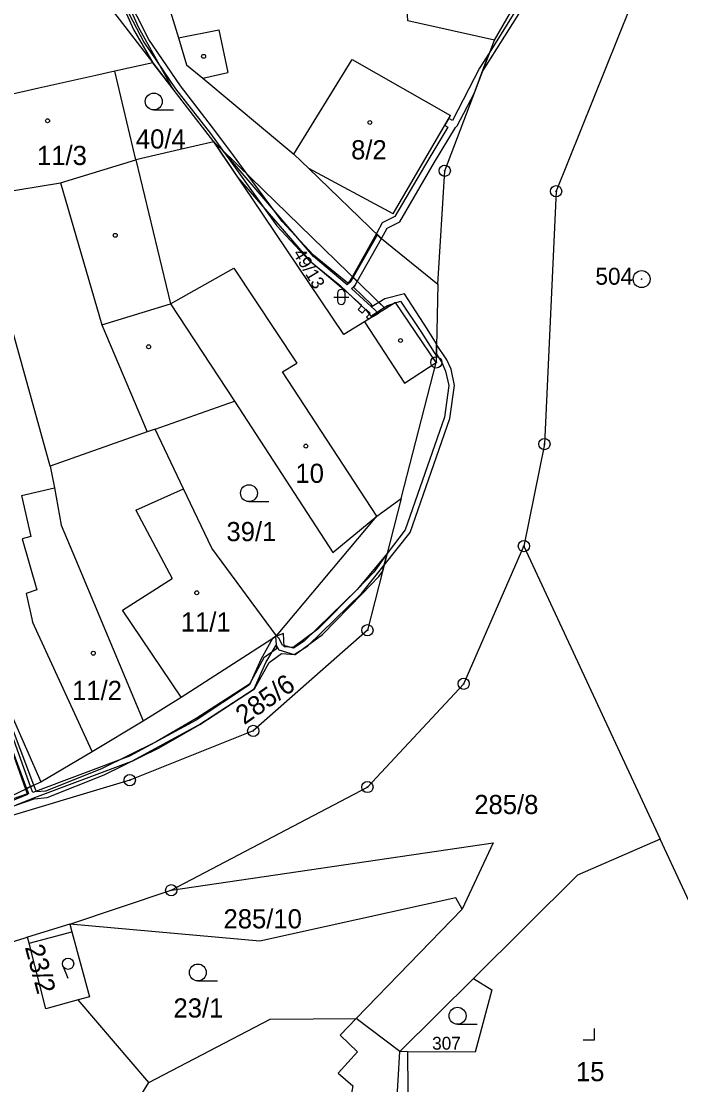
# Model space of a CAD drawing. Extents: x -779723 to -777378, y -1011169 to -1009297.
# Drawn here: x -779071.4 to -779012.9, y -1010301.7 to -1010207.4 of the extents above; entities that cross this region are included whole.
import ezdxf

# ---------------------------------------------------------------- set-up
doc = ezdxf.new("R2010")
doc.units = 0
for name, color, linetype in [('Hranice parcel', 7, 'Continuous'), ('Parcelní čísla', 7, 'Continuous'), ('Vnitřní kresba', 7, 'Continuous'), ('Věcná břemena k části', 7, 'Continuous'), ('Značky bodu BP', 7, 'Continuous'), ('Značky budov', 7, 'Continuous'), ('Značky kultur', 7, 'Continuous')]:
    doc.layers.add(name, color=color, linetype=linetype)

msp = doc.modelspace()

# ---------------------------------------------------------------- linework, layer by layer
at = {"layer": 'Hranice parcel'}
for p, q in [((-779029.4, -1010209.06), (-779023.53, -1010198.94)), ((-779059.7, -1010211.07), (-779063.08, -1010211.82)), ((-779054.29, -1010218.08), (-779059.7, -1010211.07)), ((-779061.2, -1010219.69), (-779063.08, -1010211.82)), ((-779039.06, -1010232.9), (-779054.29, -1010218.08)), ((-779034.42, -1010230.71), (-779034.55, -1010237.65)), ((-779068.8, -1010246.85), (-779072.13, -1010234.9)), ((-779037.66, -1010249.73), (-779034.55, -1010237.65)), ((-779059.5, -1010243.56), (-779052.46, -1010241.08)), ((-779039.84, -1010251.3), (-779037.66, -1010249.73)), ((-779048.74, -1010261.92), (-779039.84, -1010251.3)), ((-779026.78, -1010253.95), (-779014.69, -1010279.95)), ((-779065.1, -1010272.18), (-779060.55, -1010269.44)), ((-779069.64, -1010274.85), (-779065.1, -1010272.18)), ((-779073.55, -1010276.72), (-779069.64, -1010274.85)), ((-779009.89, -1010290.29), (-779014.69, -1010279.95)), ((-779067.08, -1010287.5), (-779058.07, -1010284.48)), ((-779041.67, -1010295.86), (-779032.26, -1010286.16)), ((-779067.08, -1010287.5), (-779070.83, -1010288.65)), ((-779037.78, -1010298.79), (-779031.26, -1010292.31)), ((-779060.06, -1010301.54), (-779066.34, -1010294.21)), ((-779037.78, -1010298.79), (-779041.67, -1010295.86)), ((-779038.46, -1010309.75), (-779037.78, -1010298.79)), ((-779037.1, -1010298.8), (-779037.78, -1010298.79))]:
    msp.add_line(p, q, dxfattribs=at)
for points in [[(-778951.52, -1010304.9), (-778950.58, -1010287.37), (-778950.58, -1010286.9), (-778950.34, -1010251.89), (-778953.35, -1010232.46), (-778955.45, -1010215), (-778962.68, -1010202.09), (-778972.6, -1010193.75), (-778987.54, -1010189.4), (-778999.84, -1010191.68), (-779009.45, -1010195.21), (-779017.34, -1010206.13), (-779023.92, -1010222.47), (-779024.96, -1010244.9), (-779026.78, -1010253.95)], [(-779029.4, -1010209.06), (-779037.09, -1010207.36), (-779037.33, -1010202.84), (-779037.65, -1010196.93), (-779037.72, -1010195.64)], [(-779067.78, -1010200.61), (-779062.19, -1010207.85), (-779059.7, -1010211.07)], [(-779058.6, -1010204.99), (-779057.43, -1010208.85), (-779056.71, -1010211.24), (-779055.26, -1010212.45), (-779047.2, -1010219.18), (-779045.87, -1010220.45), (-779039.55, -1010226.53), (-779034.42, -1010230.71)], [(-779034.42, -1010230.71), (-779033.8, -1010220.65), (-779029.4, -1010209.06)], [(-779063.08, -1010211.82), (-779064.77, -1010212.2), (-779069.82, -1010213.33), (-779076.2, -1010214.76)], [(-779054.29, -1010218.08), (-779057.29, -1010218.78), (-779061.2, -1010219.69)], [(-779039.06, -1010232.9), (-779040.92, -1010234.04), (-779042.77, -1010235.17), (-779050.87, -1010223.15), (-779054.29, -1010218.08)], [(-779061.2, -1010219.69), (-779058.14, -1010232.46), (-779052.46, -1010241.08)], [(-779034.55, -1010237.65), (-779038.16, -1010232.35), (-779039.06, -1010232.9)], [(-779052.46, -1010241.08), (-779043.73, -1010254.53), (-779039.84, -1010251.3)], [(-779059.5, -1010243.56), (-779060.22, -1010243.82), (-779068.8, -1010246.85)], [(-779048.74, -1010261.92), (-779054.48, -1010254.13), (-779056.98, -1010248.86), (-779059.5, -1010243.56)], [(-779068.8, -1010246.85), (-779068.44, -1010248.79), (-779067.83, -1010252.08), (-779066.56, -1010255.1), (-779060.55, -1010269.44)], [(-779037.66, -1010249.73), (-779040.66, -1010261.41), (-779050.79, -1010270.34), (-779061.75, -1010274.71), (-779086.5, -1010282.14)], [(-779076.54, -1010251.4), (-779075.23, -1010259.6), (-779074.39, -1010263.13), (-779072.64, -1010267.9), (-779072.39, -1010268.55), (-779072.2, -1010269.07), (-779069.64, -1010274.85)], [(-779058.07, -1010284.48), (-779040.66, -1010275.32), (-779032.12, -1010266.16), (-779026.78, -1010253.95)], [(-779060.55, -1010269.44), (-779057.2, -1010267.35), (-779048.74, -1010261.92)], [(-779014.69, -1010279.95), (-779022.02, -1010283.13), (-779031.26, -1010292.31)], [(-779058.07, -1010284.48), (-779029.51, -1010280.26), (-779032.26, -1010286.16)], [(-779032.26, -1010286.16), (-779032.82, -1010285.16), (-779050.21, -1010289), (-779067.08, -1010287.5)], [(-779067.08, -1010287.5), (-779066.89, -1010288.17), (-779065.31, -1010293.92), (-779066.34, -1010294.21)], [(-779070.83, -1010288.65), (-779071.05, -1010288.72), (-779076.63, -1010290.43), (-779079.33, -1010290.64), (-779090.04, -1010291.48)], [(-779066.34, -1010294.21), (-779069.19, -1010295.01), (-779070.69, -1010289.16), (-779070.83, -1010288.65)], [(-779037.1, -1010298.8), (-779036.94, -1010319.12), (-779030.77, -1010318.99), (-779025.76, -1010314.84), (-779021.61, -1010311.89), (-779003.74, -1010303.52), (-779004.9, -1010301.02), (-779009.89, -1010290.29)], [(-779031.26, -1010292.31), (-779029.63, -1010293.31), (-779031.09, -1010298.84), (-779037.1, -1010298.8)], [(-779041.67, -1010295.86), (-779043.09, -1010297.32), (-779041.55, -1010298.82), (-779043.27, -1010300.7), (-779041.95, -1010301.84), (-779043.36, -1010309.37), (-779048.83, -1010303.23), (-779063.1, -1010315.51), (-779057.77, -1010321.93), (-779062.91, -1010326.41), (-779058.85, -1010331.38)], [(-779060.06, -1010301.54), (-779049.3, -1010295.9), (-779041.67, -1010295.86)], [(-779095.54, -1010337.04), (-779070.4, -1010318.23), (-779060.06, -1010301.54)]]:
    msp.add_lwpolyline(points, dxfattribs=at)
at = {"layer": 'Vnitřní kresba'}
for p, q in [((-779057.43, -1010208.85), (-779053.86, -1010208.15)), ((-779053.86, -1010208.15), (-779053.04, -1010211.92)), ((-779047.2, -1010219.18), (-779042.03, -1010210.78)), ((-779042.03, -1010210.78), (-779033.28, -1010215.75)), ((-779055.26, -1010212.45), (-779053.04, -1010211.92)), ((-779038.39, -1010224.47), (-779033.28, -1010215.75)), ((-779067.91, -1010221.73), (-779061.2, -1010219.69)), ((-779038.39, -1010224.47), (-779045.87, -1010220.45)), ((-779074.94, -1010222.88), (-779067.91, -1010221.73)), ((-779067.91, -1010221.73), (-779064.23, -1010234.32)), ((-779058.14, -1010232.46), (-779052.52, -1010229.28)), ((-779052.52, -1010229.28), (-779046.93, -1010237.71)), ((-779064.23, -1010234.32), (-779058.14, -1010232.46)), ((-779064.23, -1010234.32), (-779060.22, -1010243.82)), ((-779040.92, -1010234.04), (-779037.38, -1010239.5)), ((-779037.38, -1010239.5), (-779034.55, -1010237.65)), ((-779048.2, -1010238.48), (-779046.93, -1010237.71)), ((-779039.84, -1010251.3), (-779048.2, -1010238.48)), ((-779071.35, -1010249.46), (-779068.44, -1010248.79)), ((-779061.2, -1010250.75), (-779056.98, -1010248.86)), ((-779061.2, -1010250.75), (-779057.98, -1010256.83)), ((-779062.39, -1010259.63), (-779057.98, -1010256.83)), ((-779057.2, -1010267.35), (-779062.39, -1010259.63)), ((-779065.1, -1010272.18), (-779070.38, -1010260.68)), ((-779070.69, -1010289.16), (-779066.89, -1010288.17))]:
    msp.add_line(p, q, dxfattribs=at)
msp.add_lwpolyline([(-779071.35, -1010249.46), (-779070.54, -1010253.09), (-779071.3, -1010253.31), (-779070, -1010257.83), (-779070.95, -1010258.14), (-779070.38, -1010260.68)], dxfattribs=at)
at = {"layer": 'Věcná břemena k části'}
for points in [[(-779030.46, -1010211.85), (-779022.51, -1010199.29), (-779020.23, -1010195.48), (-779019.73, -1010194.2), (-779020.75, -1010195.48), (-779022.93, -1010199.03), (-779029.85, -1010210.23)], [(-779057.92, -1010213.38), (-779060.97, -1010207.9), (-779063.22, -1010202.83), (-779063.98, -1010199.42), (-779064.47, -1010199.57), (-779063.7, -1010202.99), (-779061.41, -1010208.12), (-779059.7, -1010211.07)], [(-779051.34, -1010220.95), (-779052.56, -1010219.3), (-779054.19, -1010217.07), (-779057.26, -1010213.11), (-779060.05, -1010209.02), (-779063.16, -1010202.87), (-779063.71, -1010199.33), (-779064.28, -1010199.51), (-779063.74, -1010203.05), (-779060.51, -1010209.23), (-779057.68, -1010213.39), (-779054.6, -1010217.35), (-779053.53, -1010218.82)], [(-779039.41, -1010226.65), (-779038.9, -1010225.74), (-779037.8, -1010225.17), (-779034.7, -1010219.9), (-779032.85, -1010216.81), (-779032.7, -1010216.68), (-779031.2, -1010213.79), (-779029.85, -1010210.23), (-779030.71, -1010211.56), (-779033.12, -1010216.19), (-779033.44, -1010216.02), (-779033.8, -1010216.63), (-779033.53, -1010216.77), (-779035.22, -1010219.6), (-779038.22, -1010224.71), (-779039.34, -1010225.28), (-779039.87, -1010226.22)], [(-779040.11, -1010233.54), (-779039.68, -1010233.28), (-779040.65, -1010232.41), (-779042.08, -1010231.1), (-779041.79, -1010230.85), (-779041.56, -1010230.47), (-779041.94, -1010230.1), (-779042.19, -1010230.53), (-779042.46, -1010230.77), (-779045.46, -1010228.27), (-779053.53, -1010218.82), (-779054.29, -1010218.08), (-779052.18, -1010221.21), (-779045.81, -1010228.62), (-779042.6, -1010231.29), (-779041.17, -1010232.6), (-779041.49, -1010232.95), (-779041.13, -1010233.29), (-779040.8, -1010232.94), (-779040.43, -1010233.28), (-779040.73, -1010233.63), (-779040.53, -1010233.8)], [(-779039.17, -1010232.79), (-779039.64, -1010232.33), (-779040.23, -1010232.69), (-779040.29, -1010232.51), (-779041.91, -1010230.98), (-779041.73, -1010230.78), (-779041.56, -1010230.47), (-779042, -1010230.04), (-779042.21, -1010230.42), (-779042.4, -1010230.62), (-779045.45, -1010228.13), (-779048.24, -1010225.15), (-779051.34, -1010220.95), (-779053.53, -1010218.82), (-779052.96, -1010219.6), (-779048.7, -1010225.55), (-779045.87, -1010228.57), (-779043.09, -1010230.83), (-779040.77, -1010233.03), (-779040.36, -1010233.54)], [(-779039.41, -1010226.65), (-779039.55, -1010226.53), (-779039.87, -1010226.22), (-779042, -1010230.04), (-779041.56, -1010230.47)], [(-779039.41, -1010226.65), (-779039.55, -1010226.53), (-779039.78, -1010226.3), (-779041.94, -1010230.1), (-779041.56, -1010230.47)], [(-779034.54, -1010237.09), (-779034.52, -1010235.99), (-779035.35, -1010234.67), (-779037.38, -1010231.56), (-779039.12, -1010232.01), (-779039.64, -1010232.33), (-779039.17, -1010232.79), (-779038.88, -1010232.61), (-779037.73, -1010232.21), (-779035.85, -1010234.99)], [(-779032.93, -1010239.69), (-779033.24, -1010238.26), (-779033.62, -1010237.42), (-779034.52, -1010236.06), (-779034.54, -1010236.93), (-779034.05, -1010237.66), (-779033.72, -1010238.42), (-779033.43, -1010239.71), (-779033.82, -1010242.51), (-779037.32, -1010252.51), (-779038.91, -1010254.59), (-779039.17, -1010255.63), (-779036.88, -1010252.75), (-779033.34, -1010242.63)], [(-779086.16, -1010255.06), (-779081.79, -1010253.63), (-779080.27, -1010253.17), (-779077.7, -1010252.31), (-779075.82, -1010261.01), (-779073.45, -1010268.66), (-779071, -1010275.5), (-779070.55, -1010275.28), (-779072.9, -1010268.73), (-779072.39, -1010268.55), (-779072.58, -1010268.05), (-779073.06, -1010268.25), (-779075.34, -1010260.89), (-779077.32, -1010251.65), (-779080.43, -1010252.7), (-779081.71, -1010253.08), (-779082.28, -1010251.4), (-779082.82, -1010251.51), (-779082.19, -1010253.23), (-779086.49, -1010254.64), (-779086.96, -1010254.87), (-779086.74, -1010255.32), (-779086.19, -1010255.37)], [(-779082.82, -1010251.51), (-779082.37, -1010253.12), (-779086.74, -1010254.64), (-779086.54, -1010255.25), (-779085.5, -1010254.95), (-779081.84, -1010253.68), (-779080.28, -1010253.27), (-779077.74, -1010252.42), (-779075.74, -1010261.75), (-779073.46, -1010268.65), (-779070.9, -1010275.45), (-779070.27, -1010275.15), (-779072.69, -1010268.7), (-779072.39, -1010268.55), (-779072.64, -1010267.9), (-779072.92, -1010268.04), (-779075.06, -1010261.57), (-779077.22, -1010251.5), (-779080.48, -1010252.59), (-779081.7, -1010252.91), (-779082.13, -1010251.37)]]:
    msp.add_lwpolyline(points, close=True, dxfattribs=at)
for points in [[(-779073.35, -1010277.43), (-779070.23, -1010276.37), (-779069.09, -1010276.26), (-779064.01, -1010274.25), (-779059.14, -1010271.83), (-779055.54, -1010269.77), (-779050.67, -1010266.62), (-779049.38, -1010264.26), (-779048.29, -1010263.48), (-779047.06, -1010263.57), (-779044.66, -1010261.78), (-779041.12, -1010258.18), (-779039.64, -1010256.65), (-779039.32, -1010256.2), (-779038.91, -1010254.59), (-779040.1, -1010256.27), (-779041.54, -1010257.76), (-779045.06, -1010261.32), (-779047.24, -1010262.95), (-779048.05, -1010262.89), (-779048.12, -1010261.71), (-779048.81, -1010261.96), (-779048.74, -1010263.06), (-779049.84, -1010263.86), (-779051.13, -1010266.2), (-779055.86, -1010269.25), (-779059.42, -1010271.31), (-779064.25, -1010273.71), (-779069.23, -1010275.68), (-779070.04, -1010275.75), (-779070.27, -1010275.15), (-779070.9, -1010275.45), (-779070.73, -1010275.9), (-779073.57, -1010276.87)], [(-779073.18, -1010277.47), (-779070.42, -1010276.35), (-779061.58, -1010273.03), (-779055.61, -1010269.8), (-779050.72, -1010266.6), (-779049.67, -1010264.26), (-779048.75, -1010262.75), (-779048.53, -1010263.16), (-779047.15, -1010263.55), (-779045.96, -1010262.79), (-779041.18, -1010258.14), (-779039.17, -1010255.63), (-779038.91, -1010254.59), (-779041.56, -1010257.8), (-779046.28, -1010262.39), (-779047.23, -1010263.01), (-779048.19, -1010262.74), (-779048.51, -1010262.12), (-779048.74, -1010261.92), (-779049.09, -1010262.15), (-779050.11, -1010264.02), (-779051.12, -1010266.26), (-779055.87, -1010269.38), (-779061.78, -1010272.57), (-779070.36, -1010275.8), (-779070.55, -1010275.28), (-779071, -1010275.5), (-779070.83, -1010275.98), (-779073.36, -1010277.01)]]:
    msp.add_lwpolyline(points, dxfattribs=at)
at = {"layer": 'Značky bodu BP'}
for centre, radius in [((-779033.8, -1010220.65), 0.5), ((-779033.8, -1010220.65), 0.0303), ((-779023.92, -1010222.47), 0.5), ((-779023.92, -1010222.47), 0.0303), ((-779016.33, -1010230.26), 0.75), ((-779016.33, -1010230.26), 0.03), ((-779034.55, -1010237.65), 0.5), ((-779034.55, -1010237.65), 0.0303), ((-779024.96, -1010244.9), 0.5), ((-779024.96, -1010244.9), 0.0303), ((-779026.78, -1010253.95), 0.5), ((-779026.78, -1010253.95), 0.0303), ((-779040.66, -1010261.41), 0.5), ((-779040.66, -1010261.41), 0.0303), ((-779032.12, -1010266.16), 0.5), ((-779032.12, -1010266.16), 0.0303), ((-779050.79, -1010270.34), 0.5), ((-779050.79, -1010270.34), 0.0303), ((-779061.75, -1010274.71), 0.5), ((-779061.75, -1010274.71), 0.0303), ((-779040.66, -1010275.32), 0.5), ((-779040.66, -1010275.32), 0.0303), ((-779058.07, -1010284.48), 0.5), ((-779058.07, -1010284.48), 0.0303)]:
    msp.add_circle(centre, radius, dxfattribs=at)
at = {"layer": 'Značky budov'}
for centre in [(-779055.197, -1010210.499), (-779069.047, -1010216.219), (-779040.447, -1010216.369), (-779063.037, -1010226.379), (-779037.727, -1010235.709), (-779060.077, -1010236.269), (-779046.127, -1010245.079), (-779055.807, -1010258.089), (-779064.987, -1010263.449)]:
    msp.add_circle(centre, 0.175, dxfattribs=at)
at = {"layer": 'Značky kultur'}
for p, q in [((-779059.623, -1010215.26), (-779057.873, -1010215.26)), ((-779043.651, -1010231.851), (-779042.309, -1010231.851)), ((-779043.315, -1010231.515), (-779043.315, -1010232.186)), ((-779042.645, -1010232.186), (-779042.645, -1010231.515)), ((-779051.173, -1010250), (-779049.423, -1010250)), ((-779067.688, -1010291.184), (-779067.249, -1010292.272)), ((-779055.713, -1010292.52), (-779053.963, -1010292.52)), ((-779032.663, -1010296.36), (-779030.913, -1010296.36)), ((-779020.51, -1010297.75), (-779020.51, -1010296.75)), ((-779021.511, -1010297.75), (-779020.51, -1010297.75))]:
    msp.add_line(p, q, dxfattribs=at)
for centre, radius in [((-779059.623, -1010214.51), 0.75), ((-779051.173, -1010249.25), 0.75), ((-779067.222, -1010290.996), 0.502), ((-779055.713, -1010291.77), 0.75), ((-779032.663, -1010295.61), 0.75)]:
    msp.add_circle(centre, radius, dxfattribs=at)
for centre, start, end in [((-779042.98, -1010231.516), 0, 180), ((-779042.98, -1010232.186), 180, 359.98789)]:
    msp.add_arc(centre, 0.335, start, end, dxfattribs=at)

# ---------------------------------------------------------------- texts
at = {"layer": 'Parcelní čísla'}
for s, height, p in [('40/4', 1.7, (-779061.21, -1010218.679)), ('8/2', 1.7, (-779042.108, -1010219.64)), ('11/3', 1.7, (-779069.98, -1010220.14)), ('10', 1.7, (-779047.05, -1010248.34)), ('39/1', 1.7, (-779053.17, -1010253.51)), ('11/1', 1.7, (-779057.22, -1010261.53)), ('11/2', 1.7, (-779066.87, -1010267.6)), ('285/8', 1.7, (-779031.18, -1010277.72)), ('285/10', 1.7, (-779053.43, -1010287.86)), ('23/1', 1.7, (-779057.87, -1010295.77)), ('307', 1.14, (-779034.92, -1010298.62)), ('15', 1.7, (-779022.16, -1010301.419))]:
    msp.add_text(s, height=height, dxfattribs=at).set_placement(p)
for s, height, rotation, p in [('49/13', 1.14, 301, (-779047.308, -1010227.983)), ('285/6', 1.7, 35, (-779051.594, -1010269.847)), ('23/2', 1.7, 285, (-779071.071, -1010289.519))]:
    msp.add_text(s, height=height, rotation=rotation, dxfattribs=at).set_placement(p)
at = {"layer": 'Značky bodu BP'}
msp.add_text('504', height=1.5, dxfattribs=at).set_placement((-779020.433, -1010230.76))

doc.saveas('drawing.dxf')
